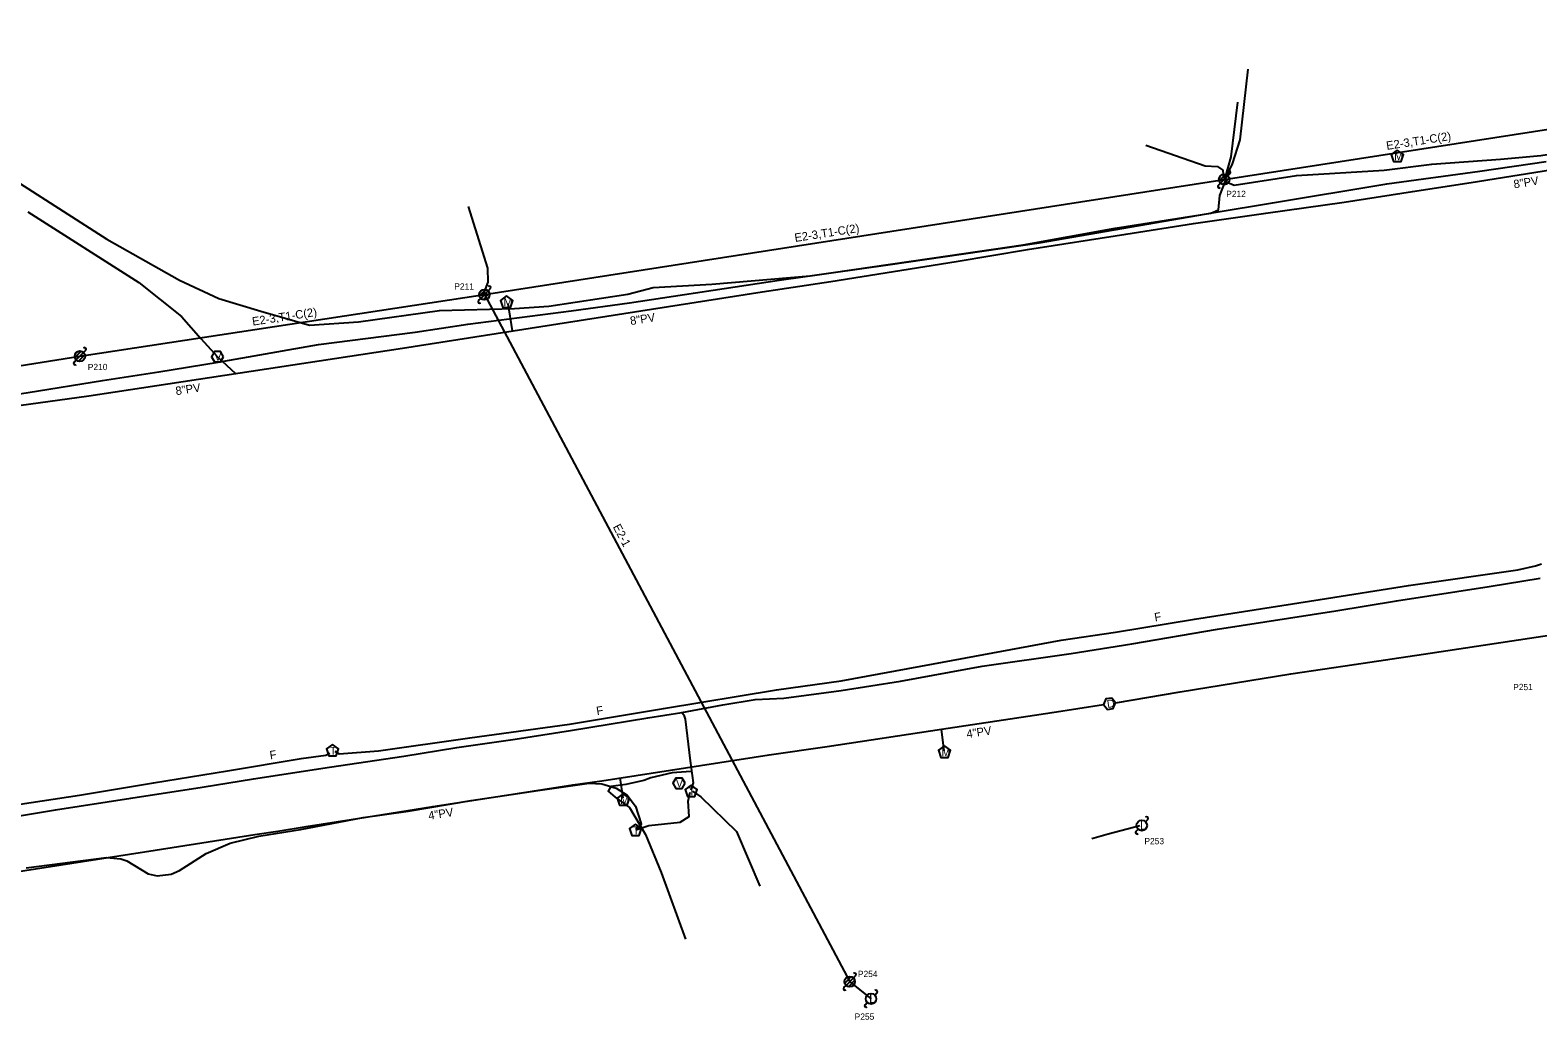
# Model space of a CAD drawing. Extents: x 1741604 to 1825760, y 1164229 to 1194908.
# Drawn here: x 1774346 to 1775065, y 1179541 to 1180013 of the extents above; entities that cross this region are included whole.
import ezdxf

# ---------------------------------------------------------------- set-up
doc = ezdxf.new("R2010")
doc.units = 0
for name, color, linetype in [('RD_EX_SU_Elec', 7, 'Continuous'), ('RD_EX_SU_H2O', 7, 'Continuous'), ('RD_EX_SU_Ovhd', 7, 'Continuous'), ('RD_EX_SU_Pole', 7, 'Continuous'), ('RD_EX_SU_Telecom', 7, 'Continuous'), ('RD_EX_SU_TX_H2O', 7, 'Continuous'), ('RD_EX_SU_TX_Pole', 7, 'Continuous'), ('RD_EX_SU_TX_Telecom', 7, 'Continuous')]:
    doc.layers.add(name, color=color, linetype=linetype)

# ---------------------------------------------------------------- blocks, each defined once
blk = doc.blocks.new('SUE_WV')
at = {"layer": 'RD_EX_SU_H2O'}
blk.add_lwpolyline([(2.89, 0), (1.44, 2.5), (-1.44, 2.5), (-2.89, 0), (-1.44, -2.5), (1.44, -2.5)], close=True, dxfattribs=at)
blk.add_text('V', height=3.75, dxfattribs=at).set_placement((-1.43, -1.88))
blk = doc.blocks.new('SUE_TPP')
at = {"layer": 'RD_EX_SU_Telecom'}
blk.add_lwpolyline([(0, 3), (-2.85, 0.93), (-1.76, -2.43), (1.76, -2.43), (2.85, 0.93)], close=True, dxfattribs=at)
blk.add_text('T', height=3.75, dxfattribs=at).set_placement((-1.25, -1.88))
blk = doc.blocks.new('SUE_WM')
at = {"layer": 'RD_EX_SU_H2O'}
blk.add_lwpolyline([(0, 3.05), (-2.9, 0.94), (-1.79, -2.47), (1.79, -2.47), (2.9, 0.94)], close=True, dxfattribs=at)
blk.add_text('M', height=3.75, dxfattribs=at).set_placement((-1.43, -1.88))

msp = doc.modelspace()

# ---------------------------------------------------------------- linework, layer by layer
at = {"layer": 'RD_EX_SU_Elec'}
for points in [[(1774916.25, 1179942.7), (1774919.1, 1179952.84), (1774922.26, 1179978.94)], [(1774555.08, 1179929.09), (1774564.29, 1179899.72), (1774564.41, 1179893.09), (1774561.67, 1179885.87)], [(1774852.52, 1179627.55), (1774860.33, 1179629.86), (1774875.4, 1179633.84)]]:
    msp.add_lwpolyline(points, dxfattribs=at)
at = {"layer": 'RD_EX_SU_H2O'}
for p, q in [((1774573.94, 1179882.85), (1774575.99, 1179869.76)), ((1774782.06, 1179669.44), (1774780.83, 1179679.7)), ((1774629.01, 1179647.06), (1774627.54, 1179656.49))]:
    msp.add_line(p, q, dxfattribs=at)
for points in [[(1774386.57, 1179840.75), (1774523.66, 1179861.56), (1774695.31, 1179888.47), (1774727.98, 1179893.39), (1774787.79, 1179902.93), (1774821.83, 1179908.67), (1774868.74, 1179915.98), (1774901.09, 1179920.97), (1774935.63, 1179925.97), (1774973.03, 1179931.27), (1775005.49, 1179936.37), (1775033.48, 1179940.52), (1775079.31, 1179947.86)], [(1774344.93, 1179926.6), (1774397.84, 1179892.85), (1774418.28, 1179876.72), (1774427.52, 1179866.21), (1774435.39, 1179857.45), (1774444.06, 1179849.47)], [(1774340.65, 1179834.22), (1774374.01, 1179838.85), (1774386.57, 1179840.75)], [(1774863.89, 1179692.35), (1774894.76, 1179697.63), (1774947.51, 1179706.13), (1774977.79, 1179710.67), (1775010.86, 1179715.58), (1775118.28, 1179731.85)], [(1774780.83, 1179679.7), (1774798.85, 1179682.43), (1774833.58, 1179687.75), (1774858.18, 1179691.48)], [(1774726.3, 1179671.45), (1774780.83, 1179679.7)], [(1774658.71, 1179661.33), (1774698.65, 1179667.53), (1774726.3, 1179671.45)], [(1774618.77, 1179655.13), (1774658.71, 1179661.33)], [(1774453.3, 1179629.47), (1774464.17, 1179631.16), (1774477.78, 1179633.32), (1774506.4, 1179637.81), (1774538.15, 1179642.86), (1774571.3, 1179648.03), (1774604.98, 1179653.23), (1774618.77, 1179655.13)], [(1774405.62, 1179622.06), (1774453.3, 1179629.47)], [(1774192.53, 1179589.02), (1774326.1, 1179609.7), (1774405.62, 1179622.06)]]:
    msp.add_lwpolyline(points, dxfattribs=at)
msp.add_lwpolyline([(1774863.89, 1179692.35), (1774862.08, 1179694.6), (1774859.23, 1179694.17), (1774858.18, 1179691.48), (1774859.98, 1179689.23), (1774862.83, 1179689.66)], close=True, dxfattribs=at)
at = {"layer": 'RD_EX_SU_Ovhd'}
for p, q in [((1774915.73, 1179942.05), (1775173.97, 1179982.14)), ((1774562.77, 1179887.09), (1774915.73, 1179942.05)), ((1774369.81, 1179857.7), (1774562.77, 1179887.09)), ((1774562.77, 1179887.09), (1774737.07, 1179559.31)), ((1774171.34, 1179826.61), (1774369.81, 1179857.7)), ((1774737.07, 1179559.31), (1774747.23, 1179551.14))]:
    msp.add_line(p, q, dxfattribs=at)
at = {"layer": 'RD_EX_SU_Pole'}
for p, q in [((1774912.9, 1179939.22), (1774913.96, 1179940.28)), ((1774913.32, 1179941.4), (1774916.38, 1179944.46)), ((1774913.96, 1179940.28), (1774917.5, 1179943.81)), ((1774915.08, 1179939.63), (1774918.15, 1179942.69)), ((1774917.5, 1179943.81), (1774918.56, 1179944.87)), ((1774560.35, 1179886.44), (1774563.42, 1179889.5)), ((1774561, 1179885.32), (1774564.54, 1179888.86)), ((1774562.12, 1179884.67), (1774565.18, 1179887.74)), ((1774564.54, 1179888.86), (1774565.6, 1179889.92)), ((1774559.94, 1179884.26), (1774561, 1179885.32)), ((1774367.39, 1179857.05), (1774370.45, 1179860.12)), ((1774368.04, 1179855.93), (1774371.57, 1179859.47)), ((1774371.57, 1179859.47), (1774372.64, 1179860.53)), ((1774366.98, 1179854.87), (1774368.04, 1179855.93)), ((1774369.16, 1179855.29), (1774372.22, 1179858.35)), ((1774878.18, 1179635.61), (1774879.24, 1179636.67)), ((1774873.59, 1179631.01), (1774874.65, 1179632.07)), ((1774734.25, 1179556.48), (1774735.31, 1179557.54)), ((1774734.66, 1179558.66), (1774737.72, 1179561.73)), ((1774735.31, 1179557.54), (1774738.84, 1179561.08)), ((1774736.43, 1179556.9), (1774739.49, 1179559.96)), ((1774738.84, 1179561.08), (1774739.9, 1179562.14)), ((1774744.4, 1179548.31), (1774745.46, 1179549.37)), ((1774749, 1179552.91), (1774750.06, 1179553.97))]:
    msp.add_line(p, q, dxfattribs=at)
for centre in [(1774915.73, 1179942.05), (1774562.77, 1179887.09), (1774369.81, 1179857.7), (1774876.41, 1179633.84), (1774737.07, 1179559.31), (1774747.23, 1179551.14)]:
    msp.add_circle(centre, 2.5, dxfattribs=at)
for centre, start, end in [((1774918.03, 1179945.4), 315, 135), ((1774913.43, 1179938.69), 135, 315), ((1774565.07, 1179890.45), 315, 135), ((1774560.47, 1179883.73), 135, 315), ((1774372.1, 1179861.06), 315, 135), ((1774367.51, 1179854.34), 135, 315), ((1774878.71, 1179637.2), 315, 135), ((1774874.12, 1179630.48), 135, 315), ((1774734.78, 1179555.95), 135, 315), ((1774739.37, 1179562.67), 315, 135), ((1774749.53, 1179554.5), 315, 135), ((1774744.93, 1179547.78), 135, 315)]:
    msp.add_arc(centre, 0.75, start, end, dxfattribs=at)
at = {"layer": 'RD_EX_SU_Telecom'}
for points in [[(1774916.38, 1179941.03), (1774920.42, 1179939.36), (1774950.29, 1179943.85), (1774992.02, 1179946.41), (1775014.85, 1179949.27), (1775047.5, 1179951.68), (1775066.74, 1179953.51), (1775123.7, 1179962.38), (1775145.09, 1179965.59), (1775170.3, 1179968.62), (1775201.86, 1179975.29), (1775224.39, 1179978.23), (1775259.05, 1179984.49), (1775284.41, 1179989.29), (1775327.61, 1179996.37), (1775362.32, 1180003.4), (1775379.35, 1180007.42), (1775383.77, 1180009.8), (1775387.12, 1180013.27)], [(1774916.23, 1179942.18), (1774919.75, 1179949.43), (1774923.28, 1179960.9), (1774927.12, 1179994.59)], [(1774878.31, 1179958.36), (1774906.57, 1179948.59), (1774912.58, 1179948.25), (1774915.01, 1179946.48), (1774915.43, 1179942.56)], [(1774435.74, 1179854.84), (1774483.67, 1179863.32), (1774529.75, 1179869.23), (1774554.79, 1179873.02), (1774604.11, 1179879.42), (1774631.95, 1179883.15), (1774703.48, 1179893.93), (1774755.23, 1179901.37), (1774827.43, 1179911.81), (1774910.96, 1179926.22), (1774938.82, 1179930.9), (1774993.33, 1179939.9), (1775037.74, 1179945.93), (1775069.26, 1179950.59)], [(1774340.99, 1179940.26), (1774382.62, 1179913.61), (1774417.31, 1179893.92), (1774436.08, 1179885.26), (1774456.05, 1179879.25), (1774479.3, 1179872.58), (1774502.65, 1179874.1), (1774541.39, 1179879.58), (1774577.11, 1179880.52), (1774593.47, 1179881.56), (1774631.18, 1179887.27), (1774643.23, 1179890.49), (1774671.27, 1179892.14), (1774718.13, 1179896.08), (1774776.31, 1179904.43), (1774819.81, 1179910.79), (1774863.67, 1179918.78), (1774909.36, 1179926), (1774913.01, 1179927.52), (1774913.67, 1179934.38), (1774916.52, 1179941.77)], [(1774172.04, 1179827.21), (1774179.79, 1179817.75), (1774181.31, 1179816.34), (1774184.57, 1179816.38), (1774196.78, 1179818.34), (1774221.01, 1179821.82), (1774246.55, 1179825.53), (1774273.46, 1179829.39), (1774311.87, 1179835.21), (1774345.11, 1179840.4), (1774380.61, 1179846.19), (1774407.39, 1179850.22), (1774435.74, 1179854.84)], [(1774491.43, 1179669.27), (1774493.51, 1179668.05), (1774512.21, 1179669.38), (1774555.82, 1179675.6), (1774603.37, 1179682.19), (1774648.25, 1179689.7), (1774702.14, 1179698.58), (1774733.03, 1179702.79), (1774777.05, 1179710.91), (1774837.88, 1179722.22), (1774863.84, 1179726.03), (1774901.59, 1179732.2), (1774961.49, 1179741.64), (1775003.61, 1179748.24), (1775055.87, 1179755.76), (1775064.29, 1179757.64), (1775067.09, 1179758.58)], [(1774661.45, 1179650.62), (1774662.47, 1179654.14), (1774661.1, 1179664.73), (1774658.65, 1179684.5), (1774658.29, 1179685.94), (1774657.04, 1179687.78), (1774676.55, 1179691.39), (1774692.02, 1179693.88), (1774705.62, 1179694.55), (1774733.01, 1179698.27), (1774761.23, 1179702.67), (1774800.26, 1179709.9), (1774842.67, 1179715.91), (1774871.59, 1179720.5), (1774912.48, 1179727.45), (1774968.92, 1179736.16), (1774997.91, 1179740.95), (1775042.08, 1179747.91), (1775066.5, 1179751.84)], [(1774488.83, 1179661.59), (1774524.41, 1179666.82), (1774549.59, 1179671.05), (1774577.5, 1179674.99), (1774603.78, 1179679.17), (1774640.76, 1179685.21), (1774657.04, 1179687.78)], [(1774333.9, 1179642.83), (1774369.52, 1179648.32), (1774404.9, 1179654.24), (1774440.15, 1179659.96), (1774475.43, 1179665.74), (1774487.06, 1179667.4), (1774489, 1179668.4)], [(1774116.37, 1179610.42), (1774117.08, 1179606.32), (1774117.49, 1179603.31), (1774150.39, 1179608.77), (1774193.48, 1179615.14), (1774217.19, 1179619.77), (1774240.88, 1179622.74), (1774276.24, 1179628.64), (1774298.79, 1179633.56), (1774322.6, 1179635.43), (1774358.12, 1179641.25), (1774394.1, 1179646.89), (1774428.11, 1179652.14), (1774452.57, 1179656.07), (1774488.83, 1179661.59)], [(1774661.32, 1179659.65), (1774652.43, 1179658.94), (1774642.2, 1179656.58), (1774638.89, 1179655.33), (1774630.27, 1179653.36), (1774623.04, 1179652.41), (1774621.9, 1179650.21), (1774625.21, 1179647.26), (1774631.98, 1179642.36), (1774639.6, 1179629.49), (1774647.12, 1179611.32), (1774658.75, 1179579.61)], [(1774344.09, 1179613.57), (1774382.42, 1179618.55), (1774389.29, 1179617.85), (1774392.25, 1179616.94), (1774402.4, 1179610.81), (1774406.72, 1179609.75), (1774413.31, 1179610.57), (1774417.35, 1179612.31), (1774429.96, 1179620.45), (1774441.48, 1179625.34), (1774455.12, 1179628.66), (1774474.99, 1179631.91), (1774504.95, 1179637.69), (1774526.36, 1179640.6), (1774556.43, 1179645.68), (1774588.27, 1179650.45), (1774612.78, 1179654.01), (1774618.8, 1179653.69), (1774625.67, 1179651.62), (1774630.94, 1179648.22), (1774634.8, 1179643.09), (1774637.62, 1179634.55), (1774637.02, 1179633.37), (1774634.8, 1179631.94)], [(1774662.08, 1179650.27), (1774665.96, 1179647.44), (1774683.04, 1179630.9), (1774694.19, 1179604.83)], [(1774635.04, 1179631.8), (1774641.15, 1179633.76), (1774656.1, 1179635.46), (1774660.48, 1179638.1), (1774659.96, 1179645.48), (1774660.93, 1179649.67)]]:
    msp.add_lwpolyline(points, dxfattribs=at)

# ---------------------------------------------------------------- block references
at = {"layer": 'RD_EX_SU_H2O'}
for name, p in [('SUE_WM', (1774998.3, 1179953.04)), ('SUE_WM', (1774573.37, 1179883.39)), ('SUE_WV', (1774435.39, 1179857.45)), ('SUE_WM', (1774782.27, 1179668.76)), ('SUE_WV', (1774655.61, 1179653.94)), ('SUE_WM', (1774629.03, 1179645.94))]:
    msp.add_blockref(name, p, dxfattribs=at)
at = {"layer": 'RD_EX_SU_Telecom'}
for p in [(1774490.35, 1179669.43), (1774661.39, 1179650.1), (1774634.84, 1179631.5)]:
    msp.add_blockref('SUE_TPP', p, dxfattribs=at)

# ---------------------------------------------------------------- texts
at = {"layer": 'RD_EX_SU_H2O'}
msp.add_text('D', height=3.75, rotation=8.63018, dxfattribs=at).set_placement((1774860.07, 1179689.87))
at = {"layer": 'RD_EX_SU_Ovhd'}
for s, rotation, p in [('E2-3,T1-C(2)', 8.82447, (1774993.36, 1179956.12)), ('E2-3,T1-C(2)', 8.85013, (1774711.06, 1179912.2)), ('E2-3,T1-C(2)', 8.65934, (1774452.27, 1179872.28)), ('E2-1', 298.00331, (1774623.94, 1179776.32))]:
    msp.add_text(s, height=4, rotation=rotation, dxfattribs=at).set_placement(p)
at = {"layer": 'RD_EX_SU_Pole'}
for p in [(1774875.55, 1179631.84), (1774746.37, 1179549.14)]:
    msp.add_text('L', height=4, dxfattribs=at).set_placement(p)
at = {"layer": 'RD_EX_SU_TX_H2O'}
for s, rotation, p in [('8"PV', 9.10403, (1775054.11, 1179937.75)), ('8"PV', 8.90979, (1774632.61, 1179872.56)), ('8"PV', 8.63102, (1774415.73, 1179839.11)), ('4"PV', 8.71325, (1774793.09, 1179675.48)), ('4"PV', 8.8588, (1774536.33, 1179636.51))]:
    msp.add_text(s, height=4, rotation=rotation, dxfattribs=at).set_placement(p)
at = {"layer": 'RD_EX_SU_TX_Pole'}
for s, p in [('P212', (1774916.7, 1179933.64)), ('P211', (1774548.42, 1179889.49)), ('P210', (1774373.56, 1179851.07)), ('P251', (1775053.61, 1179698.39)), ('P253', (1774877.66, 1179624.89)), ('P254', (1774740.97, 1179561.5)), ('P255', (1774739.43, 1179541.14))]:
    msp.add_text(s, height=3, dxfattribs=at).set_placement(p)
at = {"layer": 'RD_EX_SU_TX_Telecom'}
for rotation, p in [(9.27517, (1774882.76, 1179731.15)), (9.49836, (1774616.51, 1179686.42)), (9.29618, (1774460.66, 1179665.35))]:
    msp.add_text('F', height=4, rotation=rotation, dxfattribs=at).set_placement(p)

doc.saveas('drawing.dxf')
